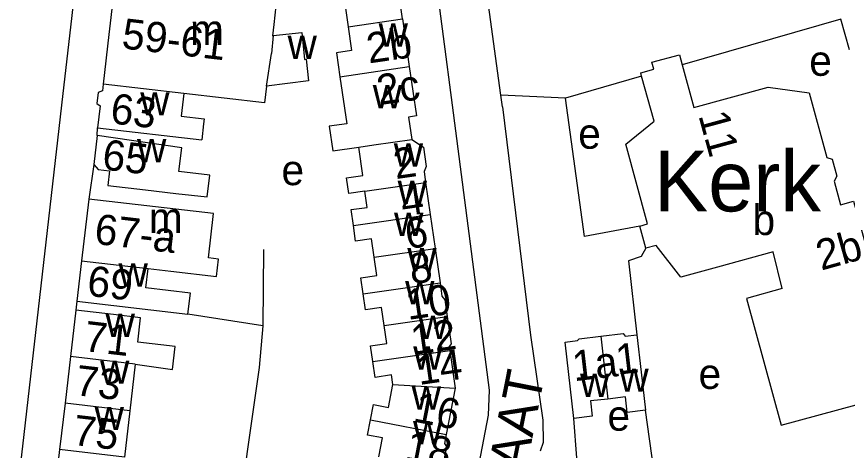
# Model space of a CAD drawing. Extents: x 161258 to 163262, y 380749 to 382054.
# Drawn here: x 162318.8 to 162428.3, y 381293.5 to 381350.8 of the extents above; entities that cross this region are included whole.
import ezdxf

# ---------------------------------------------------------------- set-up
doc = ezdxf.new("R2010")
doc.units = 0
for name, color, linetype in [('BLT_Basislijn', 7, 'Continuous'), ('BLT_Bebouwing', 7, 'Continuous'), ('BLT_Bebouwing_beschrifting', 7, 'Continuous'), ('BLT_Centroide', 7, 'Continuous'), ('BLT_Huisnummer', 7, 'Continuous'), ('BLT_Huisnummer_ tussenligend', 7, 'Continuous'), ('BLT_Huisnummer_reeks', 7, 'Continuous'), ('BLT_Onderverdeling_panden', 7, 'Continuous'), ('BLT_Straatnaam', 7, 'Continuous')]:
    doc.layers.add(name, color=color, linetype=linetype)

msp = doc.modelspace()

# ---------------------------------------------------------------- linework, layer by layer
at = {"layer": 'BLT_Basislijn'}
for p, q in [((162382.67, 381340.42), (162380.2, 381358.32)), ((162427.47, 381350.44), (162406.57, 381344.44)), ((162428.59, 381346.39), (162427.47, 381350.44)), ((162401.22, 381342.95), (162391.18, 381340.05)), ((162382.88, 381338.9), (162382.67, 381340.42)), ((162391.18, 381340.05), (162382.67, 381340.42)), ((162329.47, 381335.11), (162329.52, 381336.13)), ((162329.02, 381331.29), (162328.34, 381326.72)), ((162351.39, 381320.08), (162351.28, 381309.97)), ((162326.76, 381313.24), (162326.65, 381312.05)), ((162351.28, 381309.97), (162341.41, 381311.52)), ((162402.85, 381290.77), (162401.73, 381298.84)), ((162392.68, 381292.55), (162392.3, 381297.77))]:
    msp.add_line(p, q, dxfattribs=at)
for points in [[(162333.77, 381362.06), (162327.65, 381363.04), (162327.49, 381362.81), (162324.77, 381339.11), (162311.57, 381224.14), (162311.63, 381220.74), (162314.97, 381220.26)], [(162353.89, 381359.7), (162373.57, 381357.57), (162373.89, 381357.26), (162376.24, 381339.11), (162381.11, 381301.49), (162381, 381298.21), (162368.16, 381231.2), (162363.15, 381232.24)], [(162400.96, 381323.14), (162393.69, 381321.76), (162391.18, 381340.05)], [(162382.88, 381338.9), (162386.59, 381308.76), (162388.21, 381297.56), (162388.23, 381294.6), (162387.83, 381293.45)], [(162401.75, 381320.22), (162401.14, 381319.14), (162399.5, 381318.55), (162400.58, 381308.82)], [(162351.28, 381309.97), (162350.82, 381304.5), (162341.01, 381235.68)]]:
    msp.add_lwpolyline(points, dxfattribs=at)
at = {"layer": 'BLT_Bebouwing'}
for p, q in [((162331.75, 381354.72), (162331.01, 381348.44)), ((162369.69, 381350.49), (162370.59, 381344.23)), ((162331.01, 381348.44), (162330.24, 381341.89)), ((162329.52, 381336.13), (162343.23, 381334.52)), ((162329.47, 381335.11), (162329.02, 381331.29)), ((162372.75, 381328.9), (162373.35, 381324.69)), ((162328.34, 381326.72), (162327.39, 381318.58)), ((162373.35, 381324.69), (162374, 381320.18)), ((162401.75, 381320.22), (162400.96, 381323.14)), ((162374, 381320.18), (162374.65, 381315.67)), ((162327.39, 381318.58), (162326.76, 381313.24)), ((162419.74, 381314.9), (162415.03, 381313.61)), ((162326.65, 381312.05), (162325.94, 381305.92)), ((162375.92, 381306.72), (162376.64, 381301.74)), ((162325.94, 381305.92), (162325.22, 381299.79)), ((162334.47, 381304.93), (162333.76, 381298.79)), ((162376.64, 381301.74), (162375.46, 381295.65)), ((162325.22, 381299.79), (162324.5, 381293.65)), ((162333.76, 381298.79), (162333.04, 381292.66)), ((162324.5, 381293.65), (162323.78, 381287.52))]:
    msp.add_line(p, q, dxfattribs=at)
for points in [[(162369.69, 381350.49), (162368.76, 381356.92), (162361.57, 381355.89), (162361.28, 381357.91), (162357.15, 381357.31), (162357.87, 381352.36), (162359.01, 381352.49), (162362.05, 381352.83), (162362.53, 381349.46)], [(162353.01, 381352.23), (162352.72, 381349.73), (162352.55, 381348.27), (162352.66, 381348.28)], [(162362.53, 381349.46), (162362.98, 381346.31), (162361, 381346.02), (162361.46, 381342.83)], [(162352.66, 381348.28), (162356.41, 381348.68), (162356.8, 381345.15), (162357.01, 381345.17), (162357.32, 381342.33), (162351.76, 381341.61)], [(162401.22, 381342.95), (162401.1, 381343.38), (162402.84, 381343.86), (162402.58, 381344.78), (162406.2, 381345.77), (162406.57, 381344.44)], [(162370.59, 381344.23), (162371.53, 381337.69), (162370.48, 381337.54), (162370.91, 381334.58)], [(162406.57, 381344.44), (162408.1, 381338.82), (162417.88, 381341.49), (162423.28, 381340.74), (162425.62, 381332.18), (162426.34, 381331.99), (162426.96, 381329.74), (162426.57, 381329.07), (162427.41, 381325.97), (162429.15, 381326.44), (162432.24, 381315.14), (162430.53, 381314.67)], [(162361.46, 381342.83), (162362.35, 381336.66), (162360.05, 381336.33), (162360.52, 381333.09), (162363.93, 381333.58)], [(162400.96, 381323.14), (162402, 381323.43), (162399.12, 381333.96), (162402.85, 381336.98), (162401.22, 381342.95)], [(162330.24, 381341.89), (162330.14, 381341.02), (162329.6, 381340.79), (162329.43, 381339.33), (162329.86, 381339.01), (162329.52, 381336.13)], [(162351.76, 381341.61), (162351.5, 381339.4), (162340.87, 381340.64)], [(162340.87, 381340.64), (162340.52, 381337.65), (162343.54, 381337.29), (162343.46, 381336.63), (162343.23, 381334.52)], [(162329.02, 381331.29), (162329.57, 381330.6), (162331.1, 381330.42), (162330.88, 381328.52), (162335.84, 381327.94), (162339.84, 381327.47), (162343.96, 381326.99), (162344.3, 381329.88), (162340.23, 381330.36), (162340.6, 381333.49), (162329.47, 381335.11)], [(162370.91, 381334.58), (162372.46, 381333.55), (162372.82, 381331.03), (162372.54, 381330.34), (162372.75, 381328.9)], [(162364.73, 381327.75), (162362.62, 381327.45), (162362.32, 381329.53), (162364.46, 381329.84), (162363.93, 381333.58)], [(162363.22, 381323.23), (162362.92, 381325.32), (162365.04, 381325.62), (162364.73, 381327.75)], [(162336.18, 381317.55), (162339.17, 381317.2), (162345.17, 381316.49), (162345.45, 381318.8), (162344.12, 381318.96), (162344.81, 381324.79), (162328.34, 381326.72)], [(162365.97, 381319.03), (162365.63, 381321.45), (162363.52, 381321.15), (162363.22, 381323.23)], [(162406.38, 381316.43), (162403.12, 381320.6), (162401.75, 381320.22)], [(162419.74, 381314.9), (162418.55, 381319.75), (162411.2, 381317.75), (162406.38, 381316.43)], [(162364.52, 381314.21), (162364.22, 381316.31), (162366.32, 381316.61), (162365.97, 381319.03)], [(162341.41, 381311.52), (162341.74, 381314.3), (162335.88, 381314.99), (162336.18, 381317.55)], [(162374.65, 381315.67), (162374.9, 381313.91), (162375.28, 381313.43), (162375.6, 381311.22)], [(162367.28, 381310.02), (162366.94, 381312.41), (162364.82, 381312.1), (162364.52, 381314.21)], [(162326.76, 381313.24), (162341.41, 381311.52)], [(162415.03, 381313.61), (162419.61, 381296.87), (162429.47, 381299.56), (162434.3, 381300.88)], [(162334.47, 381304.93), (162339.38, 381304.22), (162339.74, 381307.26), (162334.81, 381307.84), (162335.19, 381311.05), (162331.62, 381311.47), (162326.65, 381312.05)], [(162375.6, 381311.22), (162376.12, 381307.61), (162375.85, 381307.26), (162375.92, 381306.72)], [(162365.79, 381305.26), (162365.49, 381307.33), (162367.62, 381307.64), (162367.28, 381310.02)], [(162395.83, 381308.62), (162398.8, 381308.97), (162399.04, 381308.64), (162400.58, 381308.82)], [(162400.58, 381308.82), (162401.15, 381303.86), (162401.73, 381298.84)], [(162392.3, 381297.77), (162391.14, 381307.84), (162392.76, 381308.03), (162392.97, 381308.29), (162395.83, 381308.62)], [(162368.44, 381302.25), (162368.25, 381303.5), (162366.09, 381303.19), (162365.79, 381305.26)], [(162365.46, 381297.59), (162365.86, 381299.61), (162367.86, 381299.22), (162368.44, 381302.25)], [(162396.78, 381300.33), (162394.48, 381300.07), (162394.71, 381298.05), (162392.3, 381297.77)], [(162401.73, 381298.84), (162399.33, 381298.57), (162399.09, 381300.6), (162396.78, 381300.33)], [(162366.56, 381292.69), (162367.05, 381295.2), (162365.07, 381295.58), (162365.46, 381297.59)], [(162375.46, 381295.65), (162375.22, 381294.46), (162375.49, 381294.06), (162374.91, 381291.07)]]:
    msp.add_lwpolyline(points, dxfattribs=at)
at = {"layer": 'BLT_Onderverdeling_panden'}
for p, q in [((162362.53, 381349.46), (162369.69, 381350.49)), ((162351.76, 381341.61), (162352.44, 381345.92)), ((162361.46, 381342.83), (162370.59, 381344.23)), ((162340.87, 381340.64), (162330.24, 381341.89)), ((162364.73, 381327.75), (162372.75, 381328.9)), ((162363.22, 381323.23), (162373.35, 381324.69)), ((162365.97, 381319.03), (162374, 381320.18)), ((162327.39, 381318.58), (162336.18, 381317.55)), ((162364.52, 381314.21), (162374.65, 381315.67)), ((162367.28, 381310.02), (162375.6, 381311.22)), ((162395.83, 381308.62), (162396.78, 381300.33)), ((162365.79, 381305.26), (162375.92, 381306.72)), ((162334.47, 381304.93), (162325.94, 381305.92)), ((162368.44, 381302.25), (162376.64, 381301.74)), ((162333.76, 381298.79), (162325.22, 381299.79)), ((162365.46, 381297.59), (162375.46, 381295.65)), ((162333.04, 381292.66), (162324.5, 381293.65))]:
    msp.add_line(p, q, dxfattribs=at)
for points in [[(162352.66, 381348.28), (162352.44, 381345.92)], [(162363.93, 381333.58), (162365.93, 381333.87), (162370.91, 381334.58)]]:
    msp.add_lwpolyline(points, dxfattribs=at)

# ---------------------------------------------------------------- texts
at = {"layer": 'BLT_Bebouwing_beschrifting'}
msp.add_text('Kerk', height=8, dxfattribs=at).set_placement((162402.85, 381325.09))
at = {"layer": 'BLT_Centroide'}
for s, p in [('m', (162341.7, 381347.06)), ('w', (162366.55, 381346.84)), ('w', (162354.55, 381345.22)), ('e', (162423.31, 381342.98)), ('w', (162365.78, 381338.69)), ('w', (162335.13, 381337.75)), ('e', (162392.86, 381333.36)), ('w', (162334.71, 381331.56)), ('w', (162368.55, 381331)), ('e', (162353.75, 381328.55)), ('w', (162369.06, 381326.06)), ('m', (162336.27, 381322.25)), ('b', (162415.83, 381321.97)), ('w', (162368.59, 381321.84)), ('w', (162370.33, 381317.19)), ('w', (162332.27, 381315.16)), ('w', (162370.04, 381312.84)), ('w', (162330.56, 381308.5)), ('w', (162371.78, 381308.25)), ('w', (162371.11, 381304.22)), ('w', (162329.84, 381302.34)), ('w', (162398.28, 381301.28)), ('e', (162408.72, 381301.66)), ('w', (162393.1, 381300.59)), ('w', (162370.91, 381298.94)), ('w', (162329.12, 381296.22)), ('e', (162396.71, 381296.15)), ('w', (162371.09, 381294.34))]:
    msp.add_text(s, height=4, dxfattribs=at).set_placement(p)
at = {"layer": 'BLT_Huisnummer'}
for s, rotation, p in [('2b', 8.1693, (162365.26, 381344.61)), ('2c', 8.1672, (162366.59, 381339.1)), ('63', 353.3096, (162331.08, 381336.73)), ('2', 8.1649, (162368.81, 381329.34)), ('6', 8.1751, (162370.33, 381320.1)), ('10', 8.1847, (162370.41, 381310.76)), ('71', 353.3341, (162327.58, 381306.68)), ('1', 6.5793, (162398.03, 381303.53)), ('14', 8.1633, (162371.88, 381302.17)), ('1a', 6.5793, (162392.31, 381302.67)), ('75', 353.3314, (162326.13, 381294.29)), ('18', 349.0216, (162369.88, 381292.33))]:
    msp.add_text(s, height=4, rotation=rotation, dxfattribs=at).set_placement(p)
at = {"layer": 'BLT_Huisnummer_ tussenligend'}
for s, rotation, p in [('65', 353.3096, (162330, 381330.65)), ('4', 8.1649, (162369.75, 381324.42)), ('8', 8.1751, (162370.88, 381315.46)), ('69', 353.3063, (162328, 381313.99)), ('12', 8.1847, (162371.1, 381306.12)), ('73', 353.3341, (162326.45, 381300.86)), ('16', 349.0216, (162370.97, 381297.38))]:
    msp.add_text(s, height=4, rotation=rotation, dxfattribs=at).set_placement(p)
at = {"layer": 'BLT_Huisnummer_reeks'}
for s, rotation, p in [('59-61', 353.3065, (162332.58, 381346.62)), ('11', 285.2638, (162408.68, 381337.76)), ('67-a', 353.3063, (162328.97, 381320.83)), ('2b', 15.6618, (162424.87, 381317.26))]:
    msp.add_text(s, height=4, rotation=rotation, dxfattribs=at).set_placement(p)
at = {"layer": 'BLT_Straatnaam'}
msp.add_text('HEGGENROOSSTRAAT', height=5, rotation=78.8081, dxfattribs=at).set_placement((162373.91, 381229.9))

doc.saveas('drawing.dxf')
